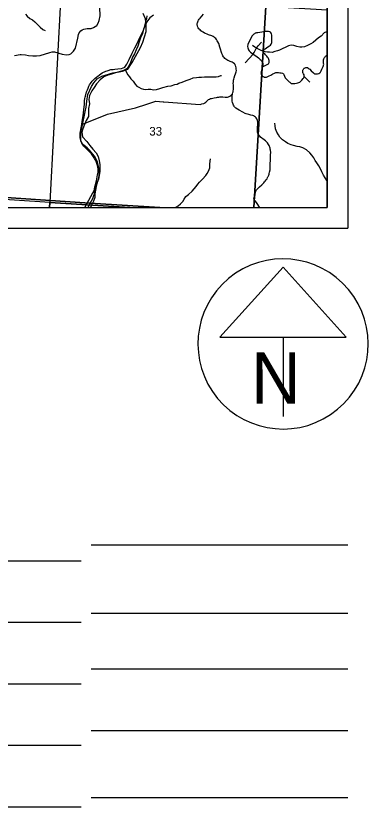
# Model space of a CAD drawing. Extents: x 0 to 82.7, y -0.2 to 22.
# Drawn here: x 7.382 to 9.099, y 11.177 to 15.035 of the extents above; entities that cross this region are included whole.
import ezdxf

# ---------------------------------------------------------------- set-up
doc = ezdxf.new("R2010")
doc.units = 0
for name, color, linetype in [('GM_X_County_Road', 7, 'Continuous'), ('GM_X_Minor_River', 7, 'Continuous'), ('GM_X_Rail_Line', 7, 'Continuous'), ('GM_X_Section', 7, 'Continuous'), ('GM_X_Section_Text', 7, 'Continuous'), ('GM_X_Township_Road', 7, 'Continuous'), ('GM_X_Township_Text', 7, 'Continuous'), ('SH_Cut_Line', 7, 'Continuous'), ('SH_Data', 7, 'Continuous')]:
    doc.layers.add(name, color=color, linetype=linetype)

msp = doc.modelspace()

# ---------------------------------------------------------------- linework, layer by layer
at = {"layer": 'GM_X_County_Road'}
for points in [[(7.9374, 14.1), (8.5415, 14.1), (8.6007, 15.0799), (7.6018, 15.1403), (7.5478, 14.1251)], [(8.5415, 14.1), (8.9, 14.1), (8.9, 15.063), (8.6007, 15.0799)], [(6.5331, 14.1), (7.5456, 14.1), (7.5478, 14.1251), (6.5375, 14.1911)], [(7.5456, 14.1), (7.9374, 14.1), (7.5478, 14.1251)]]:
    msp.add_lwpolyline(points, close=True, dxfattribs=at)
msp.add_lwpolyline([(8.5715, 14.1), (8.57, 14.1023), (8.5583, 14.1193), (8.5494, 14.131), (8.5445, 14.1387), (8.5431, 14.1421), (8.5428, 14.1442), (8.5428, 14.1465), (8.5429, 14.1486), (8.5436, 14.1509), (8.5456, 14.1545), (8.5471, 14.1583), (8.5479, 14.1602), (8.5483, 14.162), (8.5489, 14.1662), (8.5493, 14.1693), (8.5499, 14.1739), (8.5505, 14.1771), (8.5514, 14.1794), (8.5524, 14.1821), (8.5538, 14.1841), (8.5555, 14.1865), (8.5585, 14.1899), (8.5631, 14.195), (8.5705, 14.202), (8.5807, 14.2114), (8.584, 14.2142), (8.5874, 14.2177), (8.5905, 14.2209), (8.5944, 14.2253), (8.5979, 14.2295), (8.6019, 14.2347), (8.6063, 14.241), (8.6093, 14.2461), (8.6105, 14.2493), (8.6123, 14.2523), (8.6148, 14.2582), (8.6163, 14.2625), (8.6174, 14.2667), (8.6192, 14.2736), (8.621, 14.2844), (8.6222, 14.3063), (8.6237, 14.3385), (8.6239, 14.3544), (8.6242, 14.3712), (8.6239, 14.3756), (8.623, 14.3809), (8.6222, 14.3856), (8.6209, 14.3903), (8.6196, 14.3953), (8.6185, 14.3985), (8.6161, 14.4031), (8.6136, 14.4078), (8.608, 14.4159), (8.6049, 14.4195), (8.6023, 14.4223), (8.5983, 14.4261), (8.5926, 14.4305), (8.586, 14.4351), (8.5811, 14.4381), (8.5752, 14.4431), (8.5707, 14.448), (8.5674, 14.4524), (8.5646, 14.4575), (8.5621, 14.463), (8.5604, 14.4683), (8.5594, 14.4736), (8.5592, 14.4782), (8.5592, 14.4862), (8.56, 14.4937), (8.5609, 14.5041), (8.5611, 14.5119), (8.5608, 14.5173), (8.56, 14.5225), (8.5593, 14.5251), (8.558, 14.5296), (8.5563, 14.5333), (8.5528, 14.5381), (8.5503, 14.5408), (8.546, 14.5442), (8.5418, 14.5468), (8.5375, 14.5484), (8.5271, 14.5511), (8.517, 14.5534), (8.5047, 14.5569), (8.4995, 14.5592), (8.4889, 14.5653), (8.4713, 14.5748), (8.4629, 14.5798), (8.4546, 14.5848), (8.4516, 14.5875), (8.4489, 14.59), (8.4471, 14.5921), (8.4458, 14.5945), (8.4429, 14.5992), (8.4409, 14.6046), (8.4385, 14.6125), (8.4368, 14.6197), (8.4361, 14.6269), (8.4363, 14.6325), (8.4363, 14.6367), (8.4367, 14.6421), (8.4387, 14.6547), (8.4402, 14.661), (8.4409, 14.6646), (8.4418, 14.6688), (8.4426, 14.676), (8.443, 14.6826), (8.4427, 14.6903), (8.4424, 14.6985), (8.4421, 14.7059), (8.4424, 14.7133), (8.4429, 14.7192), (8.4432, 14.7219), (8.4441, 14.726), (8.4464, 14.7336), (8.45, 14.7442), (8.4529, 14.753), (8.4552, 14.7613), (8.4568, 14.7693), (8.4567, 14.7748), (8.4561, 14.7811), (8.4549, 14.7874), (8.4531, 14.7918), (8.4503, 14.7972), (8.4474, 14.8007), (8.4414, 14.806), (8.437, 14.8086), (8.4319, 14.8109), (8.4263, 14.8129), (8.4204, 14.8155), (8.4155, 14.8178), (8.41, 14.8208), (8.4053, 14.824), (8.4015, 14.8275), (8.3975, 14.832), (8.3948, 14.8354), (8.3917, 14.8404), (8.3889, 14.8452), (8.3862, 14.8514), (8.3841, 14.8568), (8.3791, 14.8718), (8.376, 14.8826), (8.3707, 14.8995), (8.3674, 14.9076), (8.3641, 14.9137), (8.3606, 14.9195), (8.3571, 14.924), (8.3524, 14.9283), (8.3483, 14.9318), (8.3436, 14.935), (8.338, 14.9378), (8.3318, 14.9398), (8.3261, 14.9412), (8.3206, 14.943), (8.3143, 14.9457), (8.3067, 14.9488), (8.3019, 14.9511), (8.2948, 14.9548), (8.2888, 14.9589), (8.284, 14.9626), (8.2799, 14.9663), (8.2764, 14.9697), (8.2744, 14.9725), (8.2713, 14.9767), (8.2694, 14.9806), (8.2675, 14.9856), (8.2667, 14.9902), (8.2664, 14.9944), (8.2667, 14.9979), (8.2674, 15.0016), (8.2685, 15.0056), (8.2701, 15.0102), (8.2725, 15.0143), (8.2759, 15.0195), (8.2802, 15.0244), (8.2974, 15.0426)], dxfattribs=at)
at = {"layer": 'GM_X_Minor_River'}
for points in [[(7.4293, 15.0433), (7.4376, 15.0327), (7.4505, 15.0228), (7.4629, 15.016), (7.4743, 15.0058), (7.4886, 14.991), (7.5011, 14.9796), (7.514, 14.969), (7.5245, 14.9633)], [(8.0528, 15.0376), (8.0358, 15.0251), (8.0213, 15.0064), (8.0122, 14.9882), (8.0038, 14.9696), (7.9989, 14.9494), (7.9894, 14.9274), (7.9833, 14.9084), (7.976, 14.8867), (7.9684, 14.8696), (7.96, 14.8506), (7.9513, 14.8335), (7.9444, 14.816), (7.9357, 14.7962), (7.9247, 14.7776), (7.9061, 14.7693), (7.8856, 14.7628), (7.8682, 14.7571), (7.8489, 14.7514), (7.8299, 14.7465), (7.8106, 14.737), (7.7928, 14.7226), (7.7757, 14.704), (7.7639, 14.6861), (7.7529, 14.669), (7.7404, 14.6473), (7.7381, 14.6268), (7.7407, 14.6059), (7.7364, 14.5834), (7.7368, 14.5659), (7.736, 14.5443), (7.7253, 14.5241), (7.7166, 14.5055), (7.7082, 14.4846), (7.704, 14.4675), (7.707, 14.445), (7.7274, 14.4218), (7.7428, 14.4024), (7.7576, 14.3853), (7.773, 14.3666), (7.7836, 14.3488), (7.7881, 14.3275), (7.7915, 14.3096), (7.7922, 14.2925), (7.7921, 14.2753), (7.7887, 14.2571), (7.7845, 14.2388), (7.778, 14.2217), (7.7742, 14.2023), (7.7707, 14.1845), (7.7665, 14.167), (7.7665, 14.1491), (7.7604, 14.1316), (7.7524, 14.1145), (7.7468, 14.1)], [(8.9, 14.9582), (8.8959, 14.9573), (8.8846, 14.9516), (8.8695, 14.9364), (8.8566, 14.9277), (8.8445, 14.9167), (8.8305, 14.9049), (8.8196, 14.8984), (8.8041, 14.8897), (8.7889, 14.884), (8.7765, 14.8821), (8.7663, 14.8825), (8.7523, 14.8863), (8.7368, 14.8912), (8.7239, 14.8916), (8.7118, 14.8885), (8.6975, 14.8825), (8.6808, 14.8749), (8.6672, 14.8684), (8.657, 14.8646), (8.6449, 14.8604), (8.6309, 14.857), (8.6192, 14.8574), (8.609, 14.8574), (8.5977, 14.8596), (8.5867, 14.8631), (8.5742, 14.8672), (8.5591, 14.8756), (8.5463, 14.8831), (8.535, 14.891)], [(7.9157, 14.7736), (7.9219, 14.7595), (7.9279, 14.7473), (7.9355, 14.7374), (7.9423, 14.7279), (7.954, 14.7161), (7.9634, 14.7017), (7.9713, 14.6914), (7.9823, 14.6868), (7.9936, 14.6803), (8.0042, 14.6769), (8.0148, 14.6757), (8.0277, 14.6768), (8.0394, 14.6775), (8.0534, 14.6748), (8.0682, 14.6759), (8.0841, 14.6804), (8.0989, 14.6849), (8.1231, 14.6916), (8.139, 14.6942), (8.1576, 14.7006), (8.1678, 14.7025), (8.1772, 14.707), (8.1932, 14.7118), (8.2049, 14.7167), (8.2174, 14.722), (8.2314, 14.7261), (8.2466, 14.7329), (8.2621, 14.7344), (8.2746, 14.7355), (8.2878, 14.7365), (8.3011, 14.7369), (8.3109, 14.7372), (8.323, 14.7376), (8.334, 14.7371), (8.3457, 14.7375), (8.3582, 14.737), (8.3692, 14.74), (8.3813, 14.7446), (8.384, 14.7445)], [(8.6543, 14.4679), (8.6471, 14.4835), (8.6467, 14.4982), (8.6452, 14.5119)], [(8.9, 14.2295), (8.898, 14.2329), (8.8897, 14.2454), (8.8822, 14.2587), (8.8742, 14.2738), (8.8648, 14.2917), (8.8587, 14.303), (8.8497, 14.319), (8.8414, 14.3303), (8.8338, 14.3432), (8.8251, 14.3557), (8.8153, 14.3679), (8.7987, 14.3815), (8.7813, 14.3917), (8.7662, 14.3959), (8.7529, 14.3986), (8.7352, 14.4031), (8.7234, 14.4065), (8.708, 14.4126), (8.6959, 14.4205), (8.6811, 14.4304), (8.669, 14.4429), (8.6622, 14.4554), (8.6543, 14.4679)], [(8.1613, 14.1), (8.1624, 14.1016), (8.1726, 14.1088), (8.1847, 14.1187), (8.1965, 14.1301), (8.2021, 14.1418), (8.2108, 14.1543), (8.2237, 14.1646), (8.2414, 14.1805), (8.2517, 14.1912), (8.2607, 14.2022), (8.2698, 14.2143), (8.2777, 14.2246), (8.2921, 14.239), (8.3076, 14.2572), (8.3148, 14.2671), (8.3212, 14.2781), (8.3277, 14.294), (8.3284, 14.3111), (8.3288, 14.3259), (8.3311, 14.3372), (8.3312, 14.3385)]]:
    msp.add_lwpolyline(points, dxfattribs=at)
at = {"layer": 'GM_X_Rail_Line'}
msp.add_lwpolyline([(7.7185, 14.1), (7.7665, 14.1901), (7.7761, 14.2127), (7.7853, 14.2387), (7.7899, 14.2645), (7.7874, 14.2928), (7.7808, 14.324), (7.7655, 14.351), (7.7397, 14.3825), (7.7297, 14.3912), (7.7221, 14.3972), (7.7086, 14.4074), (7.6997, 14.426), (7.6982, 14.4425), (7.6989, 14.4678), (7.7061, 14.496), (7.7198, 14.5676), (7.7255, 14.5905), (7.7285, 14.6183), (7.7335, 14.6521), (7.7507, 14.6903), (7.7616, 14.7092), (7.7788, 14.7275), (7.802, 14.7417), (7.8552, 14.7568), (7.8856, 14.7619), (7.9014, 14.7648), (7.9273, 14.7752), (7.9491, 14.8074), (7.9901, 14.8799), (8.0005, 14.9072), (8.0168, 14.9588), (8.0168, 14.9928), (8.0139, 15.0201), (8.0019, 15.0459)], dxfattribs=at)
at = {"layer": 'GM_X_Section'}
msp.add_lwpolyline([(7.6018, 15.1403), (7.5478, 14.1251), (6.5375, 14.1911), (6.5889, 15.2079)], close=True, dxfattribs=at)
at = {"layer": 'GM_X_Township_Road'}
for p, q in [((8.5001, 14.8052), (8.539, 14.8478)), ((8.7871, 14.7386), (8.8148, 14.7117))]:
    msp.add_line(p, q, dxfattribs=at)
for points in [[(7.3763, 14.841), (7.3853, 14.8437), (7.3938, 14.8455), (7.4032, 14.8471), (7.4087, 14.8473), (7.4292, 14.8444), (7.4439, 14.8419), (7.4647, 14.84), (7.4824, 14.8406), (7.5008, 14.8421), (7.5478, 14.8571), (7.5586, 14.8598), (7.5708, 14.8595), (7.6086, 14.8481), (7.6287, 14.8451), (7.642, 14.8473), (7.6509, 14.8506), (7.6637, 14.8631), (7.6729, 14.8772), (7.6844, 14.9261), (7.6874, 14.9436), (7.6915, 14.953), (7.6989, 14.9624), (7.7053, 14.9666), (7.7129, 14.97), (7.7294, 14.9731), (7.7495, 14.9739), (7.761, 14.9779), (7.7762, 14.9884), (7.7839, 14.9999), (7.7879, 15.0128), (7.7927, 15.0349), (7.7915, 15.0759)], [(7.7343, 14.1), (7.7446, 14.1218), (7.7505, 14.133), (7.7568, 14.1449), (7.7629, 14.1591), (7.7645, 14.1642), (7.7652, 14.1678), (7.7656, 14.173), (7.7657, 14.1818), (7.7657, 14.1896), (7.766, 14.1939), (7.7669, 14.1984), (7.7676, 14.2025), (7.7687, 14.2049), (7.7705, 14.2123), (7.7747, 14.2299), (7.7807, 14.2604), (7.7826, 14.2715), (7.7829, 14.2799), (7.7827, 14.2887), (7.7816, 14.2974), (7.7798, 14.3049), (7.7766, 14.3155), (7.7729, 14.3258), (7.7659, 14.3391), (7.7634, 14.3434), (7.7572, 14.3524), (7.7503, 14.3619), (7.7426, 14.3702), (7.7338, 14.3796), (7.7262, 14.3866), (7.7216, 14.3917), (7.7174, 14.3962), (7.7141, 14.4001), (7.7102, 14.4049), (7.7073, 14.4094), (7.7043, 14.4143), (7.7013, 14.4205), (7.6991, 14.426), (7.6968, 14.4358), (7.6961, 14.441), (7.6957, 14.4463), (7.6955, 14.45), (7.6955, 14.4539), (7.6956, 14.4586), (7.696, 14.4652), (7.6968, 14.4711), (7.6986, 14.4802), (7.7036, 14.5057), (7.7061, 14.5198), (7.7075, 14.528), (7.7105, 14.5495), (7.712, 14.5603), (7.7142, 14.5787), (7.7154, 14.5904), (7.7163, 14.6038), (7.7174, 14.6199), (7.7189, 14.6322), (7.7199, 14.6384), (7.7211, 14.6433), (7.722, 14.647), (7.7229, 14.6507), (7.7273, 14.6641), (7.7311, 14.6747), (7.7341, 14.6831), (7.7379, 14.692), (7.7416, 14.6986), (7.7455, 14.7052), (7.7491, 14.7104), (7.7541, 14.7166), (7.7586, 14.7215), (7.7661, 14.7284), (7.7694, 14.7311), (7.7812, 14.7413), (7.7894, 14.7481), (7.7958, 14.7527), (7.803, 14.7568), (7.8209, 14.7654), (7.8269, 14.7677), (7.8318, 14.7692), (7.8362, 14.7705), (7.8402, 14.7716), (7.8459, 14.7728), (7.8532, 14.7738), (7.857, 14.7742), (7.864, 14.7748), (7.8798, 14.7764), (7.8967, 14.7786), (7.9047, 14.7808), (7.9093, 14.783), (7.9131, 14.7853), (7.917, 14.7901), (7.9204, 14.7939), (7.9239, 14.7995), (7.9286, 14.8085), (7.9346, 14.8215), (7.9498, 14.8526), (7.9627, 14.8789), (7.9682, 14.8904), (7.9798, 14.9146), (7.9872, 14.9294), (7.9946, 14.9448), (8.0039, 14.9655), (8.0089, 14.9792), (8.0142, 14.998), (8.0163, 15.0063), (8.018, 15.0136), (8.0201, 15.0229), (8.0214, 15.0353)], [(8.5848, 14.7867), (8.6131, 14.8009), (8.616, 14.8039), (8.6176, 14.8082), (8.6176, 14.8138), (8.6169, 14.8177), (8.6156, 14.8224), (8.6137, 14.8268), (8.6116, 14.8303), (8.6084, 14.8339), (8.6049, 14.8381), (8.5987, 14.8452), (8.5949, 14.8492), (8.5925, 14.852), (8.5909, 14.8546), (8.5899, 14.8578), (8.5898, 14.8606), (8.5898, 14.8638), (8.5908, 14.867), (8.5921, 14.8698), (8.5946, 14.873), (8.5978, 14.8749), (8.6109, 14.8834), (8.618, 14.8882), (8.6232, 14.8918), (8.6271, 14.8973), (8.6296, 14.9048), (8.6302, 14.9261), (8.6293, 14.9416), (8.6286, 14.9466), (8.6259, 14.9513), (8.6227, 14.9547), (8.6193, 14.957), (8.6134, 14.9591), (8.6091, 14.9593), (8.6046, 14.9593), (8.5996, 14.9593), (8.5717, 14.9545), (8.5617, 14.9529), (8.5553, 14.952), (8.5514, 14.9509), (8.548, 14.9498), (8.5446, 14.9479), (8.5419, 14.9461), (8.5383, 14.9425), (8.5337, 14.9368), (8.516, 14.9036), (8.5128, 14.8959), (8.5115, 14.8861), (8.5124, 14.8787), (8.5153, 14.87), (8.5194, 14.8643), (8.5259, 14.8578), (8.539, 14.8478), (8.5524, 14.8397), (8.5583, 14.8347), (8.5644, 14.8302), (8.5702, 14.8256), (8.5736, 14.8227), (8.5771, 14.8194), (8.5797, 14.816), (8.5824, 14.8113), (8.5843, 14.807), (8.5853, 14.8025), (8.5858, 14.7975), (8.5853, 14.7927), (8.5848, 14.7867), (8.5778, 14.7625), (8.5773, 14.7595), (8.577, 14.7565), (8.5773, 14.7532), (8.5786, 14.7484), (8.5813, 14.7436), (8.5848, 14.74), (8.5872, 14.7386), (8.5902, 14.7371), (8.593, 14.7362), (8.5968, 14.7356), (8.6007, 14.7359), (8.6045, 14.7366), (8.6107, 14.7395), (8.6164, 14.7425), (8.6245, 14.7462), (8.6355, 14.752), (8.6432, 14.756), (8.649, 14.7585), (8.6525, 14.7595), (8.656, 14.7596), (8.6596, 14.7594), (8.6618, 14.759), (8.6693, 14.7576), (8.6754, 14.7569), (8.6812, 14.756), (8.6846, 14.7541), (8.6868, 14.752), (8.6889, 14.7483), (8.6921, 14.7402), (8.6951, 14.7327), (8.7023, 14.7244), (8.7135, 14.7139), (8.7168, 14.7111), (8.7202, 14.7083), (8.7245, 14.7058), (8.7282, 14.705), (8.7338, 14.7046), (8.7419, 14.7057), (8.75, 14.7065), (8.7573, 14.7078), (8.7622, 14.7095), (8.767, 14.7123), (8.7701, 14.7153), (8.7761, 14.7222), (8.7819, 14.7292), (8.7852, 14.7334), (8.7871, 14.7386), (8.7877, 14.7435), (8.7869, 14.7476), (8.7848, 14.7522), (8.7831, 14.755), (8.7816, 14.7579), (8.7807, 14.7606), (8.7802, 14.7636), (8.7805, 14.7674), (8.781, 14.7703), (8.7823, 14.773), (8.784, 14.7756), (8.7857, 14.7777), (8.7877, 14.7795), (8.7896, 14.7807), (8.7926, 14.7819), (8.7959, 14.7828), (8.7993, 14.783), (8.8032, 14.7824), (8.8076, 14.7807), (8.8115, 14.7775), (8.8147, 14.7746), (8.8217, 14.7674), (8.8309, 14.7581), (8.835, 14.7549), (8.8394, 14.753), (8.844, 14.7521), (8.852, 14.7518), (8.8581, 14.754), (8.8632, 14.7569), (8.8666, 14.7607), (8.8703, 14.7663), (8.8737, 14.775), (8.8795, 14.7879), (8.8827, 14.7991), (8.8824, 14.8024), (8.8821, 14.81), (8.8822, 14.816), (8.8823, 14.821), (8.8831, 14.8247), (8.8841, 14.8279), (8.8864, 14.8323), (8.8892, 14.836), (8.8918, 14.8389), (8.8956, 14.8419), (8.9, 14.844)], [(8.539, 14.8478), (8.5431, 14.857), (8.5527, 14.8752), (8.5626, 14.8886), (8.5801, 14.9073)], [(8.1029, 14.6158), (8.2799, 14.6033), (8.2889, 14.6063), (8.2979, 14.6081), (8.3013, 14.6089), (8.3035, 14.6107), (8.308, 14.6147), (8.3156, 14.6216), (8.3214, 14.6267), (8.3254, 14.6291), (8.3304, 14.6313), (8.3358, 14.6326), (8.349, 14.6354), (8.3595, 14.6375), (8.3653, 14.6383), (8.3716, 14.6389), (8.3767, 14.6394), (8.381, 14.6397), (8.3909, 14.6394), (8.4018, 14.6388), (8.4067, 14.6386), (8.4143, 14.6389), (8.4182, 14.6399), (8.4212, 14.641), (8.4255, 14.6434), (8.4294, 14.6463), (8.4387, 14.6547)], [(7.7036, 14.5057), (7.8283, 14.5554), (7.965, 14.587), (8.0209, 14.6048), (8.0638, 14.6185), (8.101, 14.6159), (8.1029, 14.6158)]]:
    msp.add_lwpolyline(points, dxfattribs=at)
at = {"layer": 'GM_X_Township_Text'}
msp.add_lwpolyline([(3.8036, 15.5496), (4.1209, 14.8338), (3.7187, 14.6543), (3.6092, 14.6054), (3.1288, 14.3932), (3.472, 14.3677), (3.6086, 14.371), (3.7569, 14.3626), (5.5319, 14.2622), (6.4714, 14.2058), (6.5437, 14.2015), (6.8262, 14.1829), (7.3099, 14.151), (7.7427, 14.1224), (8.0832, 14.1), (8.9, 14.1), (8.9, 20.1381)], dxfattribs=at)
msp.add_lwpolyline([(6.5387, 14.1), (8.0832, 14.1), (7.7427, 14.1224), (7.3099, 14.151), (6.8262, 14.1829), (6.5437, 14.2015)], close=True, dxfattribs=at)
at = {"layer": 'SH_Cut_Line'}
msp.add_lwpolyline([(3.8036, 15.5496), (4.1209, 14.8338), (3.7187, 14.6543), (3.6092, 14.6054), (3.1288, 14.3932), (2.4652, 14.1), (8.9, 14.1), (8.9, 20.9)], dxfattribs=at)
at = {"layer": 'SH_Data'}
for p, q in [((9, 21), (9, 14)), ((8.9, 20.9), (8.9, 14.1)), ((2.1, 14.1), (8.9, 14.1)), ((2, 14), (9, 14)), ((8.6845, 13.8091), (8.3769, 13.4678)), ((8.9921, 13.4678), (8.6845, 13.8091)), ((8.3769, 13.4678), (8.9921, 13.4678)), ((8.6845, 13.4678), (8.6845, 13.0811)), ((8.6845, 13.4353), (8.6845, 13.4353)), ((8.6845, 13.4353), (8.6845, 13.4353)), ((7.75, 12.4553), (9, 12.4553)), ((7.7, 12.3767), (4.4937, 12.3767)), ((9, 12.1207), (7.75, 12.1207)), ((7.7, 12.0767), (3.9895, 12.0767)), ((9, 11.8491), (7.75, 11.8491)), ((7.7, 11.7767), (3.6192, 11.7767)), ((9, 11.5491), (7.75, 11.5491)), ((7.7, 11.4767), (3.3288, 11.4767)), ((9, 11.2223), (7.75, 11.2223)), ((7.7, 11.1767), (4.7452, 11.1767))]:
    msp.add_line(p, q, dxfattribs=at)
msp.add_arc((8.6845, 13.4353), 0.4148, 129.7798, 129.7633, dxfattribs=at)

# ---------------------------------------------------------------- texts
at = {"layer": 'GM_X_Section_Text'}
msp.add_text('33', height=0.04186, rotation=0, dxfattribs=at).set_placement((8.0326, 14.4514))
at = {"layer": 'SH_Data'}
msp.add_text('N', height=0.25, dxfattribs=at).set_placement((8.5292, 13.144))

doc.saveas('drawing.dxf')
